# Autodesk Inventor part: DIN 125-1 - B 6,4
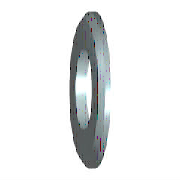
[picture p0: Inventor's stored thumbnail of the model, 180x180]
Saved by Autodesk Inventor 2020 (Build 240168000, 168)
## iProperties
IsCustomPart: 0
Created: 2010-02
Part Number: DIN 125-1 - B 6,4
Material: Steel, Mild
Document SubType Name: Modeling
Standard: DIN 125-1
Designer: DLutz
Standards Organization: DIN
Language: de-DE
Size Designation: B 6,4
Categories: <MemberInstance><Categories><Category DisplayName="Verbindungselemente" InternalName="e4da775c-781d-43d5-af7c-5136215cf5a6" Mnemonic="FSTN"><Category DisplayNam
Mass: 0.994565 g
Surface Area: 2.45302 cm^2
Volume: 0.126535 cm^3
Density: 7.86 g/cm^3
Appearance: Metal-Steel
Author: DLutz
Revision Number: C
Title: Unterlegscheibe
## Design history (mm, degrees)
chamfer "Chamfer" distance "d4" = 0.4 (= PHH); stored, may be unused: angle "d5" = 45 deg, second distance "d8" = 0.4 (= PHH)
workaxis "Work Axis1"
workplane "Work Plane1"
body "Solid1"
sketch "Sketch"
  geometry: C1 r 6 at (0, 0); C2 r 3.2 at (0, 0); 1 further point
  constraints: 2 centre point, 2 coincident
  dimensions: "d0" = 6.4 diameter of C2 (= SD1); "d1" = 12 diameter of C1 (= SD2)
extrude "Body" new body sketch "Sketch" distance "d2" = 1.6 (= SD); taper "d3" = 0 deg
other parameters: "SD1" = 6.4 [user parameter; used in 1 equation term], "SD2" = 12 [user parameter; used in 1 equation term], "SD" = 1.6 [user parameter; used in 1 equation term], "PHH" = 0.4 [user parameter; used in 2 equation terms], "FAWI" = 45 deg [user parameter], "d6" = 0, "d7" = 0, "d9" = 0, "d10" = 0, "NND" = 6 [user parameter]
